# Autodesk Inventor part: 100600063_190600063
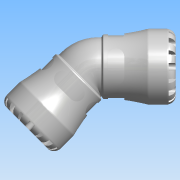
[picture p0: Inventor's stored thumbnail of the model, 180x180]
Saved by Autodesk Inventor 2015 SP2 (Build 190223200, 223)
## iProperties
Created: 2016-12
Part Number: 100600063_190600063
Material: PVC-Piping
Description: PLASSON 45° ELBOW 63-63 SERIES 1
Document SubType Name: Modeling
Designer: KIM
Mass: 664.223 g
Surface Area: 733.008 cm^2
Volume: 474.445 cm^3
Density: 1.4 g/cm^3
Appearance: Smooth - White
Author: KIM
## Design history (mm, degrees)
derived "1006.ipt"
feature "Solid1::1006.ipt"
tag "TaggingFeature1"
body "Solid1"
other parameters: "d1" = 37.8, "d2" = 63, "d3" = 78.75, "d4" = 103, "d8" = 87.55, "d13" = 9.7, "d14" = 9.7, "d15" = 0, "d17" = 360 deg, "d19" = 8 deg, "d20" = 1.26, "d21" = 1.26, "d22" = 8 deg, "d24" = 0, "d26" = 360 deg, "d33" = 10.3, "d43" = 80.34, "d51" = 1.03, "d54" = 22.05, "d55" = 13.86, "d57" = 19.012, "d58" = 0, "d74" = 0, "d77" = 5.25, "d82" = 1.26, "d115" = 360 deg, "d207" = 90 deg, "d228" = 18.7425, "d247" = 2.06, "d248" = 5.4, "d268" = 18.3855, "d269" = 5.51565, "d270" = 118, "d277" = 135 deg, "d279" = 5.51565, "d280" = 135 deg, "d281" = 0, "d282" = 0, "d_" = 63, "E_" = 103, "A_" = 118, "d9" = 12.125, "d11" = 103, "d12" = 78.75
